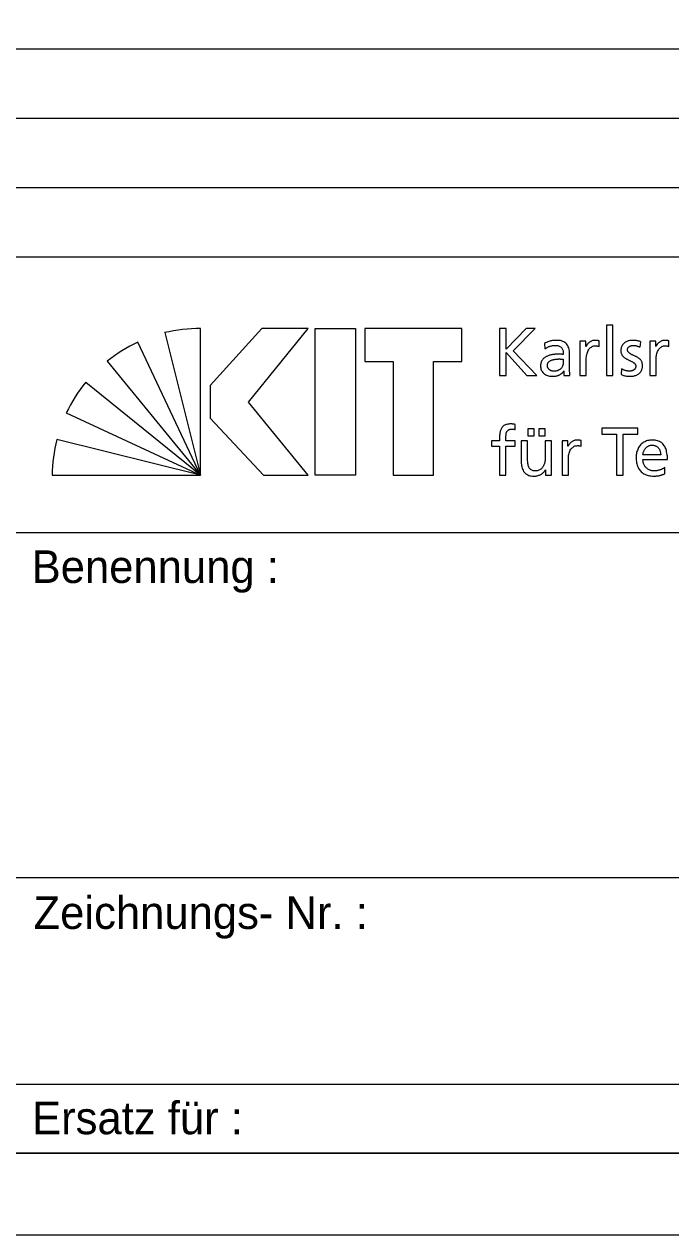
# Model space of a CAD drawing. Extents: x 0 to 21, y 0 to 14.9.
# Drawn here: x 18.816 to 19.808, y 0 to 1.856 of the extents above; entities that cross this region are included whole.
import ezdxf

# ---------------------------------------------------------------- set-up
doc = ezdxf.new("R2010")
doc.units = 0
doc.layers.add('90_Plankopf', color=7, linetype='Continuous')

msp = doc.modelspace()

# ---------------------------------------------------------------- linework, layer by layer
at = {"layer": '90_Plankopf'}
for p, q in [((16.453, 1.8185), (20.9, 1.8185)), ((16.453, 1.7123), (20.9, 1.7123)), ((16.453, 1.606), (20.9, 1.606)), ((16.453, 1.4998), (20.9, 1.4998)), ((16.453, 1.4998), (20.9, 1.4998)), ((19.0319, 1.3833), (19.087, 1.1647)), ((19.087, 1.1647), (19.087, 1.3896)), ((19.5452, 1.3897), (19.5452, 1.3176)), ((19.087, 1.1647), (18.9908, 1.3688)), ((19.6145, 1.3665), (19.615, 1.3583)), ((19.6982, 1.3621), (19.6982, 1.3708)), ((19.7614, 1.361), (19.7622, 1.3694)), ((19.8053, 1.3621), (19.8053, 1.3708)), ((18.9436, 1.3396), (19.087, 1.1647)), ((19.6433, 1.3427), (19.6433, 1.3381)), ((19.653, 1.328), (19.653, 1.3497)), ((19.7324, 1.328), (19.7319, 1.3193)), ((19.087, 1.1647), (18.9108, 1.3071)), ((19.5452, 1.3176), (19.5556, 1.3176)), ((19.5876, 1.3176), (19.6027, 1.3176)), ((18.881, 1.2603), (19.087, 1.1647)), ((19.5693, 1.2348), (19.5697, 1.2427)), ((19.087, 1.1647), (18.8664, 1.2197)), ((19.6707, 1.2091), (19.6707, 1.2178)), ((19.7927, 1.196), (19.7654, 1.196)), ((19.7654, 1.1888), (19.803, 1.1888)), ((19.7989, 1.1668), (19.7989, 1.1765)), ((18.8591, 1.1647), (19.087, 1.1647)), ((18.8, 1.0768), (20.9, 1.0768)), ((18.8, 0.548), (20.9, 0.548)), ((18.8, 0.2308), (20.9, 0.2308)), ((20.9, 0.125), (16.453, 0.125)), ((16.745, 0.125), (20.9, 0.125)), ((16.745, 0.125), (20.9, 0.125))]:
    msp.add_line(p, q, dxfattribs=at)
for points in [[(0, 0), (21.025, 0), (21.025, 14.85), (0, 14.85)], [(0.625, 14.725), (20.9, 14.725), (20.9, 0.125), (0.625, 0.125)], [(19.2517, 1.3897), (19.1809, 1.3897), (19.1018, 1.3025), (19.1018, 1.2523), (19.1834, 1.1647), (19.2521, 1.1647), (19.1606, 1.2766)], [(19.3243, 1.3897), (19.3243, 1.1647), (19.2625, 1.1647), (19.2625, 1.3897)], [(19.3391, 1.3897), (19.3391, 1.339), (19.3825, 1.339), (19.3825, 1.1647), (19.4443, 1.1647), (19.4443, 1.339), (19.4877, 1.339), (19.4877, 1.3897)]]:
    msp.add_lwpolyline(points, close=True, dxfattribs=at)
for points in [[(19.7095, 1.3176), (19.7192, 1.3176), (19.7192, 1.395), (19.7095, 1.395), (19.7095, 1.3176)], [(19.6027, 1.3176), (19.5662, 1.3556), (19.6, 1.3897), (19.5863, 1.3897), (19.5556, 1.358), (19.5556, 1.3897), (19.5452, 1.3897)], [(19.678, 1.3621), (19.6778, 1.3621), (19.6778, 1.3703), (19.6688, 1.3703), (19.6688, 1.3176), (19.6785, 1.3176), (19.6785, 1.3416)], [(19.7852, 1.3621), (19.785, 1.3621), (19.785, 1.3703), (19.7759, 1.3703), (19.7759, 1.3176), (19.7856, 1.3176), (19.7856, 1.3416)], [(19.5556, 1.3176), (19.5556, 1.3529), (19.5876, 1.3176)], [(19.6441, 1.3245), (19.6443, 1.3245), (19.6443, 1.3176), (19.6534, 1.3176)], [(19.5889, 1.2356), (19.5889, 1.2253), (19.5986, 1.2253), (19.5986, 1.2356), (19.5889, 1.2356)], [(19.6058, 1.2356), (19.6058, 1.2253), (19.6155, 1.2253), (19.6155, 1.2356), (19.6058, 1.2356)], [(19.7248, 1.1647), (19.7351, 1.1647), (19.7351, 1.2276), (19.7575, 1.2276), (19.7575, 1.2367), (19.7024, 1.2367), (19.7024, 1.2276), (19.7248, 1.2276), (19.7248, 1.1647)], [(19.5456, 1.2221), (19.5456, 1.2173), (19.5332, 1.2173), (19.5332, 1.2094), (19.5456, 1.2094), (19.5456, 1.1647), (19.5553, 1.1647), (19.5553, 1.2094), (19.5692, 1.2094), (19.5692, 1.2173), (19.5553, 1.2173), (19.5553, 1.223)], [(19.5885, 1.19), (19.5885, 1.2173), (19.5788, 1.2173), (19.5788, 1.186)], [(19.6254, 1.1647), (19.6254, 1.2173), (19.6157, 1.2173), (19.6157, 1.1929)], [(19.6506, 1.2091), (19.6504, 1.2091), (19.6504, 1.2173), (19.6413, 1.2173), (19.6413, 1.1647), (19.651, 1.1647), (19.651, 1.1886)], [(19.6158, 1.173), (19.616, 1.173), (19.616, 1.1647), (19.6254, 1.1647)]]:
    msp.add_lwpolyline(points, dxfattribs=at)
for centre, start, end in [((19.0862, 1.1514), 89.8053, 103.1895), ((19.0915, 1.1529), 115.0126, 128.3968), ((19.0954, 1.1566), 140.7898, 154.174), ((19.0973, 1.1609), 165.7222, 179.1064)]:
    msp.add_arc(centre, 0.2382, start, end, dxfattribs=at)
for points in [[(19.653, 1.3497), (19.653, 1.3545), (19.6523, 1.3585), (19.6508, 1.3617), (19.6494, 1.365), (19.6471, 1.3674), (19.644, 1.369), (19.6409, 1.3707), (19.6368, 1.3715), (19.6318, 1.3715), (19.6285, 1.3715), (19.6253, 1.371), (19.6224, 1.3701), (19.6195, 1.3692), (19.6169, 1.368), (19.6145, 1.3665)], [(19.615, 1.3583), (19.6163, 1.3594), (19.6178, 1.3604), (19.6195, 1.3611), (19.6211, 1.362), (19.6229, 1.3626), (19.6247, 1.363), (19.6266, 1.3634), (19.6284, 1.3637), (19.6303, 1.3637), (19.6335, 1.3637), (19.636, 1.3631), (19.6379, 1.3621), (19.6399, 1.3611), (19.6412, 1.3596), (19.642, 1.3575), (19.6429, 1.3555), (19.6433, 1.353), (19.6433, 1.3499)], [(19.6982, 1.3708), (19.6975, 1.3709), (19.6968, 1.371), (19.6962, 1.3712), (19.6956, 1.3713), (19.6949, 1.3713), (19.6942, 1.3714), (19.6935, 1.3715), (19.6927, 1.3715), (19.6918, 1.3715), (19.6899, 1.3715), (19.6881, 1.3711), (19.6863, 1.3703), (19.6845, 1.3695), (19.6829, 1.3684), (19.6815, 1.367), (19.6801, 1.3656), (19.6789, 1.3639), (19.678, 1.3621)], [(19.6785, 1.3416), (19.6785, 1.346), (19.6791, 1.3498), (19.6802, 1.353), (19.6814, 1.3562), (19.6831, 1.3587), (19.6852, 1.3604), (19.6874, 1.3621), (19.6899, 1.363), (19.6928, 1.363), (19.6936, 1.3631), (19.6945, 1.363), (19.6954, 1.3629), (19.6964, 1.3627), (19.6973, 1.3625), (19.6982, 1.3621)], [(19.7622, 1.3694), (19.7604, 1.37), (19.7584, 1.3705), (19.7565, 1.3709), (19.7545, 1.3713), (19.7524, 1.3715), (19.7502, 1.3715), (19.7476, 1.3715), (19.7451, 1.3712), (19.7429, 1.3705), (19.7406, 1.3698), (19.7387, 1.3688), (19.737, 1.3675), (19.7353, 1.3662), (19.734, 1.3645), (19.733, 1.3625), (19.7321, 1.3604), (19.7316, 1.358), (19.7316, 1.3553), (19.7316, 1.3532), (19.7321, 1.3514), (19.7329, 1.3498), (19.7337, 1.3483), (19.7348, 1.347), (19.7361, 1.3459), (19.7375, 1.3447), (19.739, 1.3437), (19.7406, 1.3429), (19.7422, 1.342), (19.7438, 1.3412), (19.7454, 1.3404), (19.7471, 1.3397), (19.7485, 1.3389), (19.7499, 1.338), (19.7512, 1.3373), (19.7523, 1.3363), (19.7532, 1.3353), (19.754, 1.3343), (19.7544, 1.3331), (19.7544, 1.3318), (19.7544, 1.3304), (19.7541, 1.3292), (19.7535, 1.3282), (19.7529, 1.3272), (19.7521, 1.3265), (19.7511, 1.3259), (19.7501, 1.3253), (19.7491, 1.3249), (19.7479, 1.3246), (19.7468, 1.3244), (19.7456, 1.3242), (19.7445, 1.3242), (19.7435, 1.3242), (19.7424, 1.3244), (19.741, 1.3247), (19.7396, 1.3249), (19.7381, 1.3253), (19.7366, 1.3259), (19.7351, 1.3265), (19.7337, 1.3271), (19.7324, 1.328)], [(19.7319, 1.3193), (19.7342, 1.3181), (19.7365, 1.3174), (19.7389, 1.317), (19.7414, 1.3166), (19.7439, 1.3164), (19.7464, 1.3164), (19.7487, 1.3164), (19.751, 1.3167), (19.7532, 1.3174), (19.7554, 1.318), (19.7573, 1.3191), (19.7591, 1.3204), (19.7608, 1.3217), (19.7622, 1.3234), (19.7632, 1.3255), (19.7642, 1.3276), (19.7647, 1.33), (19.7647, 1.3328), (19.7647, 1.3352), (19.7643, 1.3372), (19.7635, 1.3389), (19.7626, 1.3406), (19.7616, 1.342), (19.7602, 1.3431), (19.7589, 1.3443), (19.7574, 1.3453), (19.7557, 1.3461), (19.7541, 1.3469), (19.7525, 1.3477), (19.7509, 1.3484), (19.7493, 1.3491), (19.7478, 1.3499), (19.7464, 1.3507), (19.7451, 1.3515), (19.744, 1.3524), (19.7432, 1.3534), (19.7424, 1.3545), (19.7419, 1.3557), (19.7419, 1.3573), (19.7419, 1.3587), (19.7424, 1.3599), (19.7432, 1.3609), (19.7441, 1.3618), (19.7452, 1.3625), (19.7466, 1.363), (19.748, 1.3634), (19.7495, 1.3637), (19.7512, 1.3637), (19.7518, 1.3637), (19.7526, 1.3636), (19.7535, 1.3634), (19.7544, 1.3633), (19.7553, 1.3631), (19.7564, 1.3628), (19.7574, 1.3626), (19.7583, 1.3623), (19.7592, 1.362), (19.7601, 1.3616), (19.7609, 1.3613), (19.7614, 1.361)], [(19.8053, 1.3708), (19.8046, 1.3709), (19.804, 1.371), (19.8034, 1.3712), (19.8027, 1.3713), (19.8021, 1.3713), (19.8014, 1.3714), (19.8007, 1.3715), (19.7998, 1.3715), (19.7989, 1.3715), (19.797, 1.3715), (19.7952, 1.3711), (19.7934, 1.3703), (19.7917, 1.3695), (19.7901, 1.3684), (19.7886, 1.367), (19.7872, 1.3656), (19.786, 1.3639), (19.7852, 1.3621)], [(19.7856, 1.3416), (19.7856, 1.346), (19.7862, 1.3498), (19.7874, 1.353), (19.7886, 1.3562), (19.7902, 1.3587), (19.7923, 1.3604), (19.7945, 1.3621), (19.797, 1.363), (19.7999, 1.363), (19.8008, 1.3631), (19.8016, 1.363), (19.8026, 1.3629), (19.8035, 1.3627), (19.8044, 1.3625), (19.8053, 1.3621)], [(19.6433, 1.3499), (19.642, 1.35), (19.6408, 1.3501), (19.6397, 1.3501), (19.6386, 1.3501), (19.6376, 1.3501), (19.6365, 1.3501), (19.6354, 1.3501), (19.6342, 1.3501), (19.6329, 1.3501), (19.6309, 1.3501), (19.6288, 1.35), (19.6266, 1.3496), (19.6243, 1.3492), (19.6221, 1.3487), (19.62, 1.3478), (19.6179, 1.347), (19.616, 1.346), (19.6142, 1.3446), (19.6125, 1.3433), (19.6111, 1.3416), (19.6101, 1.3397), (19.609, 1.3377), (19.6085, 1.3354), (19.6085, 1.3328), (19.6085, 1.329), (19.6094, 1.3259), (19.611, 1.3235), (19.6126, 1.3211), (19.6149, 1.3193), (19.6177, 1.3181), (19.6206, 1.317), (19.624, 1.3164), (19.6278, 1.3164), (19.63, 1.3164), (19.632, 1.3167), (19.6338, 1.3172), (19.6355, 1.3177), (19.6371, 1.3184), (19.6384, 1.3192), (19.6398, 1.32), (19.6409, 1.3209), (19.6418, 1.3218), (19.6428, 1.3228), (19.6435, 1.3236), (19.6441, 1.3245)], [(19.6433, 1.3381), (19.6433, 1.3354), (19.6427, 1.3331), (19.6416, 1.331), (19.6405, 1.3289), (19.6388, 1.3273), (19.6367, 1.3261), (19.6345, 1.3249), (19.6318, 1.3243), (19.6286, 1.3242), (19.6275, 1.3242), (19.6264, 1.3244), (19.6252, 1.3248), (19.6241, 1.3252), (19.623, 1.3257), (19.622, 1.3264), (19.6211, 1.3272), (19.6203, 1.3281), (19.6197, 1.3291), (19.6191, 1.3302), (19.6188, 1.3314), (19.6188, 1.3328), (19.6188, 1.3347), (19.6193, 1.3362), (19.6202, 1.3374), (19.6211, 1.3387), (19.6223, 1.3396), (19.6237, 1.3404), (19.6252, 1.3411), (19.6267, 1.3417), (19.6284, 1.342), (19.63, 1.3424), (19.6316, 1.3426), (19.6332, 1.3428), (19.6347, 1.3429), (19.636, 1.3429), (19.6371, 1.3429), (19.6381, 1.3429), (19.6391, 1.3429), (19.6402, 1.3428), (19.6412, 1.3428), (19.6422, 1.3427), (19.6433, 1.3427)], [(19.6534, 1.3176), (19.6533, 1.3181), (19.6532, 1.3188), (19.6532, 1.3197), (19.6531, 1.3205), (19.6531, 1.3216), (19.653, 1.323), (19.653, 1.3243), (19.653, 1.326), (19.653, 1.328)], [(19.5697, 1.2427), (19.5688, 1.2428), (19.5678, 1.243), (19.5667, 1.2431), (19.5656, 1.2432), (19.5645, 1.2433), (19.5632, 1.2433), (19.5597, 1.2433), (19.5568, 1.2428), (19.5544, 1.2418), (19.5521, 1.2408), (19.5503, 1.2394), (19.5491, 1.2375), (19.5478, 1.2356), (19.5469, 1.2334), (19.5464, 1.2308), (19.5458, 1.2282), (19.5456, 1.2253), (19.5456, 1.2221)], [(19.5553, 1.223), (19.5553, 1.2247), (19.5554, 1.2264), (19.5556, 1.2279), (19.5558, 1.2294), (19.5562, 1.2307), (19.5569, 1.2319), (19.5575, 1.233), (19.5585, 1.2339), (19.5597, 1.2345), (19.561, 1.2351), (19.5626, 1.2354), (19.5647, 1.2354), (19.5655, 1.2354), (19.5664, 1.2354), (19.5672, 1.2353), (19.568, 1.2352), (19.5688, 1.235), (19.5693, 1.2348)], [(19.6707, 1.2178), (19.67, 1.2179), (19.6693, 1.2181), (19.6688, 1.2182), (19.6681, 1.2183), (19.6675, 1.2184), (19.6667, 1.2184), (19.6661, 1.2185), (19.6652, 1.2185), (19.6643, 1.2185), (19.6624, 1.2185), (19.6606, 1.2181), (19.6588, 1.2173), (19.6571, 1.2165), (19.6555, 1.2154), (19.654, 1.214), (19.6526, 1.2126), (19.6514, 1.211), (19.6506, 1.2091)], [(19.651, 1.1886), (19.651, 1.193), (19.6516, 1.1968), (19.6528, 1.2), (19.6539, 1.2032), (19.6556, 1.2057), (19.6577, 1.2074), (19.6599, 1.2092), (19.6624, 1.21), (19.6653, 1.21), (19.6662, 1.2101), (19.667, 1.21), (19.668, 1.2099), (19.6689, 1.2097), (19.6698, 1.2095), (19.6707, 1.2091)], [(19.803, 1.1888), (19.803, 1.1931), (19.8026, 1.197), (19.8018, 1.2006), (19.801, 1.2042), (19.7997, 1.2073), (19.7979, 1.21), (19.7961, 1.2127), (19.7938, 1.2148), (19.7908, 1.2162), (19.7878, 1.2177), (19.7841, 1.2185), (19.7797, 1.2185), (19.776, 1.2185), (19.7726, 1.2178), (19.7696, 1.2166), (19.7666, 1.2152), (19.764, 1.2134), (19.7618, 1.2111), (19.7597, 1.2087), (19.758, 1.2059), (19.7569, 1.2026), (19.7557, 1.1994), (19.7551, 1.1958), (19.7551, 1.1919), (19.7551, 1.1876), (19.7556, 1.1837), (19.7567, 1.1802), (19.7578, 1.1767), (19.7595, 1.1737), (19.7617, 1.1712), (19.7639, 1.1687), (19.7668, 1.1668), (19.7702, 1.1655), (19.7736, 1.1641), (19.7777, 1.1634), (19.7823, 1.1634), (19.7852, 1.1634), (19.7876, 1.1636), (19.7897, 1.164), (19.7917, 1.1644), (19.7934, 1.1648), (19.7949, 1.1653), (19.7964, 1.1659), (19.7977, 1.1664), (19.7989, 1.1668)], [(19.7654, 1.196), (19.7656, 1.1977), (19.766, 1.1995), (19.7666, 1.2012), (19.7672, 1.2029), (19.7681, 1.2045), (19.7692, 1.2059), (19.7703, 1.2073), (19.7717, 1.2085), (19.7734, 1.2093), (19.7751, 1.2102), (19.7772, 1.2107), (19.7795, 1.2107), (19.7816, 1.2107), (19.7835, 1.2103), (19.7851, 1.2095), (19.7867, 1.2088), (19.7881, 1.2077), (19.7892, 1.2064), (19.7903, 1.205), (19.7912, 1.2035), (19.7918, 1.2017), (19.7924, 1.1999), (19.7927, 1.1981), (19.7927, 1.196)], [(19.6157, 1.1929), (19.6157, 1.1897), (19.6154, 1.1868), (19.6147, 1.1841), (19.6141, 1.1815), (19.6131, 1.1792), (19.6118, 1.1773), (19.6105, 1.1754), (19.6088, 1.1739), (19.6068, 1.1728), (19.6048, 1.1718), (19.6024, 1.1713), (19.5997, 1.1713), (19.5969, 1.1714), (19.5947, 1.1722), (19.593, 1.1736), (19.5914, 1.175), (19.5902, 1.1771), (19.5895, 1.1798), (19.5889, 1.1825), (19.5885, 1.1859), (19.5885, 1.19)], [(19.7989, 1.1765), (19.7983, 1.176), (19.7975, 1.1755), (19.7963, 1.1749), (19.7952, 1.1743), (19.7939, 1.1737), (19.7924, 1.1732), (19.7909, 1.1726), (19.7893, 1.1722), (19.7876, 1.1718), (19.786, 1.1715), (19.7844, 1.1713), (19.7827, 1.1713), (19.7804, 1.1713), (19.7782, 1.1717), (19.7762, 1.1725), (19.7741, 1.1734), (19.7722, 1.1746), (19.7706, 1.1761), (19.769, 1.1777), (19.7677, 1.1795), (19.7668, 1.1817), (19.7659, 1.1838), (19.7654, 1.1862), (19.7654, 1.1888)], [(19.5788, 1.186), (19.5788, 1.1813), (19.5795, 1.1772), (19.5809, 1.1739), (19.5823, 1.1705), (19.5845, 1.1679), (19.5874, 1.1661), (19.5903, 1.1644), (19.594, 1.1634), (19.5986, 1.1634), (19.601, 1.1634), (19.6034, 1.1638), (19.6056, 1.1646), (19.6079, 1.1653), (19.6099, 1.1665), (19.6117, 1.1679), (19.6134, 1.1693), (19.6148, 1.171), (19.6158, 1.173)]]:
    msp.add_open_spline(points, degree=3, dxfattribs=at)

# ---------------------------------------------------------------- texts
for s, p in [('Benennung :', (18.8278, 0.9995)), ('Zeichnungs- Nr. :', (18.8307, 0.469)), ('Ersatz für :', (18.8285, 0.1542))]:
    msp.add_text(s, height=0.05, dxfattribs=at).set_placement(p)

doc.saveas('drawing.dxf')
